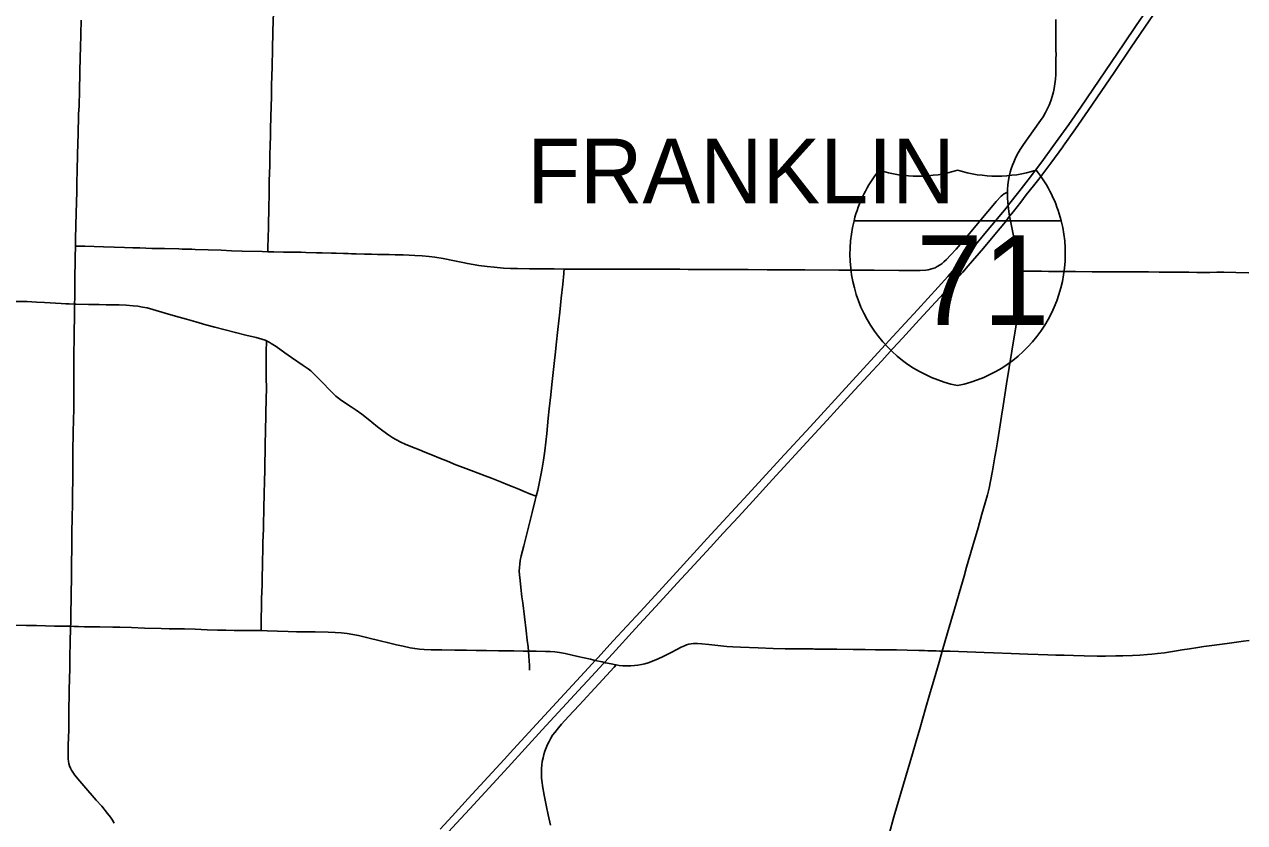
# Model space of a CAD drawing. Extents: x 1815539 to 1947826, y 273303 to 993194.
# Drawn here: x 1909139 to 1926135, y 915807 to 926931 of the extents above; entities that cross this region are included whole.
import ezdxf

# ---------------------------------------------------------------- set-up
doc = ezdxf.new("R2010")
doc.units = 0
for name, color, linetype in [('GM_X_County_Road', 7, 'Continuous'), ('GM_X_Interstate_Route', 7, 'Continuous'), ('GM_X_Interstate_Shield', 7, 'Continuous'), ('GM_X_State_Route', 7, 'Continuous'), ('GM_X_Township_Road', 7, 'Continuous'), ('GM_X_Township_Text', 7, 'Continuous')]:
    doc.layers.add(name, color=color, linetype=linetype)

msp = doc.modelspace()

# ---------------------------------------------------------------- linework, layer by layer
at = {"layer": 'GM_X_County_Road'}
for points in [[(1909852, 923839), (1909853, 923944), (1909861, 924304), (1909869, 924599), (1909872, 924714), (1909876, 924911), (1909884, 925288), (1909887, 925386), (1909895, 925681), (1909900, 925796), (1909908, 926009), (1909913, 926255), (1909917, 926484), (1909921, 926599), (1909925, 926795), (1909930, 926992)], [(1909839, 923031), (1909841, 923127), (1909842, 923288), (1909844, 923452), (1909846, 923583), (1909848, 923698), (1909851, 923829), (1909852, 923839)], [(1907174, 923151), (1907342, 923130), (1907473, 923114), (1907783, 923079), (1907946, 923061), (1908028, 923054), (1908093, 923053), (1908225, 923054), (1908569, 923063), (1908766, 923067), (1908881, 923068), (1909061, 923068), (1909176, 923067), (1909307, 923062), (1909421, 923055), (1909651, 923040), (1909715, 923038), (1909764, 923035), (1909828, 923032), (1909839, 923031)], [(1909783, 918543), (1909784, 918578), (1909788, 918742), (1909790, 918922), (1909796, 919299), (1909797, 919397), (1909799, 919660), (1909802, 919824), (1909806, 920086), (1909808, 920217), (1909811, 920397), (1909813, 920578), (1909813, 920725), (1909814, 920840), (1909815, 920988), (1909818, 921233), (1909822, 921430), (1909826, 921561), (1909829, 921807), (1909830, 921939), (1909830, 922086), (1909830, 922217), (1909830, 922331), (1909833, 922561), (1909838, 922937), (1909839, 923031)], [(1909839, 923031), (1909845, 923031), (1909860, 923031), (1910033, 923029), (1910082, 923028), (1910180, 923027), (1910278, 923024), (1910360, 923024), (1910458, 923021), (1910556, 923017), (1910654, 923010), (1910719, 923002), (1910784, 922992), (1910848, 922979), (1910927, 922959), (1911100, 922908), (1911242, 922867), (1911399, 922822), (1911526, 922786), (1911667, 922746), (1911794, 922710), (1912079, 922636), (1912223, 922601), (1912366, 922566), (1912445, 922545), (1912492, 922529), (1912511, 922521)], [(1912511, 922521), (1912522, 922517), (1912551, 922502), (1912578, 922486), (1912646, 922440), (1912766, 922354), (1912860, 922288), (1913023, 922178), (1913090, 922131), (1913129, 922101), (1913165, 922068), (1913224, 922011), (1913292, 921940), (1913392, 921832), (1913439, 921785), (1913475, 921752), (1913514, 921720), (1913554, 921692), (1913692, 921603), (1913759, 921557), (1913839, 921498), (1913903, 921448), (1913979, 921386), (1914056, 921325), (1914134, 921265), (1914215, 921208), (1914269, 921171), (1914312, 921146), (1914384, 921108), (1914444, 921079), (1914520, 921048), (1914642, 921000), (1914718, 920970), (1914823, 920927), (1914912, 920891), (1915033, 920842), (1915149, 920795), (1915212, 920771), (1915361, 920715), (1915557, 920640), (1915647, 920606), (1915783, 920550), (1915874, 920513), (1915934, 920489), (1916024, 920453), (1916099, 920423), (1916190, 920386), (1916269, 920357)], [(1916161, 918197), (1916155, 918255), (1916144, 918350), (1916128, 918480), (1916105, 918676), (1916080, 918871), (1916070, 918952), (1916054, 919082), (1916043, 919180), (1916035, 919262), (1916033, 919311), (1916034, 919361), (1916039, 919410), (1916047, 919459), (1916061, 919523), (1916097, 919666), (1916153, 919889), (1916184, 920016), (1916211, 920127), (1916255, 920301), (1916269, 920357)], [(1910391, 915798), (1910366, 915841), (1910339, 915882), (1910299, 915934), (1910216, 916035), (1910141, 916122), (1909968, 916319), (1909882, 916418), (1909841, 916470), (1909813, 916510), (1909796, 916539), (1909781, 916568), (1909769, 916598), (1909759, 916629), (1909753, 916661), (1909749, 916694), (1909748, 916743), (1909751, 916891), (1909753, 916989), (1909757, 917104), (1909758, 917186), (1909759, 917251), (1909759, 917415), (1909763, 917563), (1909765, 917661), (1909770, 917956), (1909773, 918153), (1909777, 918284), (1909779, 918366), (1909781, 918480), (1909783, 918543)], [(1918287, 918252), (1918289, 918253), (1918333, 918273), (1918363, 918285), (1918395, 918294), (1918428, 918299), (1918461, 918302), (1918515, 918302), (1918576, 918298), (1918674, 918289), (1918923, 918263), (1919006, 918255), (1919114, 918250), (1919360, 918241), (1919570, 918235), (1919734, 918231), (1919849, 918229), (1919931, 918228), (1920012, 918228), (1920062, 918227), (1920127, 918227), (1920144, 918226), (1920455, 918223), (1920685, 918220), (1920701, 918220), (1920736, 918220), (1920849, 918218), (1920992, 918217), (1921119, 918217), (1921201, 918216)], [(1921924, 918198), (1921946, 918198), (1922036, 918196), (1922149, 918193), (1922394, 918183), (1922509, 918179), (1922640, 918174), (1922886, 918164), (1923000, 918159), (1923115, 918156), (1923262, 918151), (1923393, 918146), (1923508, 918143), (1923622, 918140), (1923753, 918136), (1923901, 918132), (1924081, 918128), (1924196, 918127), (1924343, 918130), (1924441, 918132), (1924572, 918135), (1924676, 918141), (1924785, 918148), (1924845, 918153), (1924921, 918162), (1925019, 918175), (1925186, 918201), (1925264, 918213), (1925367, 918230), (1925484, 918248), (1925568, 918261), (1925680, 918275), (1925891, 918304), (1926118, 918334), (1926198, 918346)], [(1916161, 918197), (1916266, 918196), (1916396, 918194), (1916461, 918192), (1916527, 918186), (1916592, 918178), (1916673, 918163), (1916849, 918124), (1917025, 918083), (1917056, 918076)], [(1917380, 918005), (1917425, 917999), (1917474, 917994), (1917523, 917993), (1917588, 917993), (1917637, 917997), (1917685, 918003), (1917733, 918011), (1917781, 918022), (1917828, 918036), (1917889, 918058), (1917965, 918090), (1918039, 918124), (1918156, 918182), (1918287, 918252)], [(1921201, 918216), (1921285, 918215), (1921436, 918210), (1921597, 918206), (1921676, 918204), (1921724, 918202), (1921838, 918199), (1921887, 918198), (1921924, 918198)], [(1917056, 918076), (1917070, 918073), (1917091, 918068), (1917185, 918047), (1917218, 918039), (1917235, 918035), (1917313, 918018), (1917377, 918006), (1917380, 918005)]]:
    msp.add_lwpolyline(points, dxfattribs=at)
at = {"layer": 'GM_X_Interstate_Route'}
for points in [[(1923602, 925224), (1923610, 925234), (1923780, 925475), (1923958, 925731), (1924317, 926260), (1924556, 926613), (1925118, 927441), (1925224, 927597), (1925284, 927685), (1925431, 927902), (1925578, 928120), (1925818, 928472), (1926030, 928784), (1926120, 928917), (1926205, 929042)], [(1914932, 915718), (1915099, 915899), (1915320, 916142), (1915598, 916443), (1915820, 916685), (1915953, 916830), (1916274, 917181), (1916552, 917483), (1916997, 917965), (1917091, 918068), (1917099, 918077), (1917126, 918105), (1917342, 918339), (1917719, 918750), (1918075, 919137), (1918274, 919354), (1918651, 919766), (1918873, 920007), (1919218, 920381), (1919672, 920877), (1920083, 921323), (1920626, 921916), (1920926, 922242), (1921237, 922580), (1921581, 922955), (1921869, 923269), (1922001, 923416), (1922208, 923649), (1922389, 923861), (1922589, 924100), (1922694, 924226), (1922736, 924277), (1922790, 924344), (1922808, 924366), (1922840, 924408), (1922848, 924418), (1922992, 924597), (1923122, 924766), (1923310, 925015), (1923465, 925227), (1923685, 925534), (1923854, 925776), (1924451, 926659), (1924627, 926916), (1924903, 927324)], [(1922210, 923480), (1922285, 923566), (1922499, 923814), (1922658, 924002), (1922804, 924181), (1922813, 924193), (1922863, 924257), (1922915, 924322), (1922967, 924390), (1923018, 924453), (1923095, 924555), (1923197, 924682), (1923267, 924774), (1923435, 924996), (1923602, 925224)], [(1918355, 919277), (1918695, 919648), (1918873, 919841), (1919085, 920069), (1919284, 920287), (1919561, 920590), (1920038, 921109), (1920316, 921410), (1920460, 921567), (1920703, 921834), (1921081, 922244), (1921237, 922413), (1921369, 922558), (1921602, 922812), (1921890, 923127), (1922122, 923381), (1922210, 923480)], [(1916915, 917710), (1916986, 917787), (1917202, 918021), (1917218, 918039), (1917330, 918161), (1917653, 918511), (1917986, 918873), (1918285, 919201), (1918355, 919277)], [(1911986, 912380), (1912025, 912417), (1912151, 912542), (1912323, 912715), (1912448, 912846), (1913169, 913631), (1913524, 914017), (1914001, 914537), (1914234, 914790), (1914468, 915044), (1914789, 915395), (1915100, 915733), (1915344, 915999), (1915665, 916350), (1915876, 916579), (1916353, 917099), (1916915, 917710)]]:
    msp.add_lwpolyline(points, dxfattribs=at)
at = {"layer": 'GM_X_Interstate_Shield'}
for p, q in [((1920695, 924195), (1923581, 924195)), ((1923581, 924195), (1920695, 924195)), ((1923581, 924195), (1920695, 924195))]:
    msp.add_line(p, q, dxfattribs=at)
for centre, start, end in [((1922513, 923735), 141.669, 165.8066), ((1921590, 926691), 253.0091, 286.9909), ((1922686, 926691), 253.0091, 286.9909), ((1921763, 923735), 14.1934, 38.331), ((1922513, 923735), 165.8066, 258.463), ((1921763, 923735), 281.537, 14.1934)]:
    msp.add_arc(centre, 1875, start, end, dxfattribs=at)
at = {"layer": 'GM_X_State_Route'}
for points in [[(1923508, 926469), (1923509, 926493), (1923508, 926592), (1923507, 926739), (1923507, 927001)], [(1922964, 922819), (1922983, 922943), (1923010, 923122), (1923017, 923187), (1923021, 923252), (1923022, 923317), (1923020, 923382), (1923014, 923448), (1923008, 923495), (1923003, 923529), (1922975, 923690), (1922940, 923867), (1922888, 924124), (1922863, 924257), (1922858, 924285), (1922845, 924367), (1922840, 924408), (1922836, 924448), (1922832, 924514), (1922831, 924563), (1922832, 924593), (1922833, 924629), (1922839, 924695), (1922848, 924760), (1922856, 924809), (1922872, 924873), (1922885, 924920), (1922901, 924967), (1922919, 925013), (1922940, 925058), (1922969, 925116), (1923010, 925188), (1923054, 925257), (1923110, 925338), (1923293, 925590), (1923329, 925645), (1923361, 925701), (1923391, 925759), (1923411, 925804), (1923435, 925865), (1923455, 925927), (1923473, 925990), (1923484, 926037), (1923494, 926102), (1923502, 926166), (1923505, 926232), (1923508, 926395), (1923508, 926469)], [(1921187, 915666), (1921250, 915887), (1921383, 916343), (1921509, 916768), (1921560, 916941), (1921612, 917114), (1921697, 917413), (1921747, 917587), (1921810, 917807), (1921879, 918044), (1921924, 918198), (1921997, 918453), (1922043, 918611), (1922093, 918784), (1922181, 919082), (1922227, 919240), (1922263, 919366), (1922344, 919650), (1922422, 919917), (1922477, 920106), (1922523, 920263), (1922554, 920374), (1922577, 920469), (1922597, 920565), (1922623, 920710), (1922657, 920904), (1922674, 921000), (1922692, 921114), (1922720, 921292), (1922749, 921470), (1922772, 921616), (1922820, 921924), (1922892, 922377), (1922948, 922716), (1922964, 922819)]]:
    msp.add_lwpolyline(points, dxfattribs=at)
at = {"layer": 'GM_X_Township_Road'}
for points in [[(1912530, 923763), (1912532, 923817), (1912535, 923964), (1912538, 924095), (1912546, 924407), (1912548, 924538), (1912551, 924752), (1912556, 924965), (1912560, 925096), (1912564, 925260), (1912567, 925359), (1912569, 925474), (1912573, 925638), (1912578, 925792), (1912580, 925917), (1912580, 925983), (1912583, 926097), (1912585, 926196), (1912589, 926360), (1912594, 926573), (1912602, 926836), (1912607, 927099)], [(1921723, 923511), (1921730, 923511), (1921762, 923518), (1921793, 923528), (1921823, 923540), (1921853, 923555), (1921895, 923580), (1921921, 923599), (1921947, 923620), (1921983, 923653), (1922039, 923713), (1922116, 923798), (1922201, 923898), (1922297, 924010), (1922561, 924324), (1922632, 924413), (1922676, 924463), (1922743, 924535), (1922766, 924557), (1922779, 924567), (1922794, 924575), (1922832, 924593)], [(1909852, 923839), (1909914, 923839), (1909979, 923840), (1910110, 923836), (1910241, 923831), (1910389, 923825), (1910536, 923821), (1910651, 923818), (1910749, 923815), (1910831, 923812), (1910913, 923809), (1910978, 923808), (1911093, 923806), (1911289, 923801), (1911339, 923800), (1911470, 923797), (1911519, 923796), (1911699, 923791), (1911879, 923784), (1912026, 923777), (1912174, 923773), (1912452, 923765), (1912530, 923763)], [(1912530, 923763), (1912534, 923763), (1912616, 923761), (1912747, 923758), (1912846, 923757), (1912993, 923755), (1913058, 923753), (1913206, 923749), (1913288, 923748), (1913419, 923744), (1913484, 923743), (1913582, 923740), (1913648, 923737), (1913697, 923735), (1913762, 923732), (1913877, 923729), (1913975, 923727), (1914057, 923725), (1914123, 923724), (1914221, 923722), (1914302, 923721), (1914368, 923720), (1914417, 923719), (1914499, 923716), (1914580, 923712), (1914679, 923706), (1914776, 923697), (1914858, 923686), (1914971, 923667), (1915132, 923635), (1915244, 923613), (1915309, 923601), (1915470, 923573), (1915584, 923557), (1915681, 923546), (1915812, 923535), (1915910, 923529), (1916009, 923527), (1916173, 923525), (1916369, 923523), (1916517, 923523), (1916659, 923521)], [(1916269, 920357), (1916291, 920440), (1916333, 920648), (1916352, 920745), (1916370, 920858), (1916387, 920987), (1916414, 921231), (1916436, 921442), (1916449, 921573), (1916471, 921767), (1916487, 921914), (1916520, 922206), (1916538, 922369), (1916547, 922467), (1916569, 922678), (1916596, 922922), (1916607, 923020), (1916617, 923118), (1916638, 923313), (1916654, 923459), (1916655, 923476), (1916659, 923521)], [(1916659, 923521), (1916730, 923520), (1916845, 923520), (1916992, 923521), (1917090, 923521), (1917189, 923521), (1917402, 923520), (1917500, 923520), (1917730, 923519), (1918008, 923520), (1918123, 923520), (1918271, 923518), (1918385, 923517), (1918598, 923517), (1918779, 923516), (1919221, 923513), (1919484, 923512), (1919763, 923511), (1920008, 923510), (1920484, 923508), (1920746, 923508), (1920976, 923507), (1921320, 923502), (1921517, 923500), (1921615, 923503), (1921697, 923507), (1921723, 923511)], [(1923008, 923495), (1923044, 923494), (1923143, 923492), (1923307, 923490), (1923405, 923489), (1923667, 923486), (1923782, 923486), (1924012, 923485), (1924258, 923483), (1924455, 923483), (1924619, 923482), (1924799, 923482), (1924947, 923480), (1925078, 923478), (1925242, 923477), (1925357, 923476), (1925472, 923475), (1925603, 923474), (1925651, 923475), (1925749, 923476), (1925847, 923477), (1926011, 923474), (1926192, 923471)], [(1912435, 918484), (1912436, 918509), (1912436, 918525), (1912437, 918576), (1912438, 918629), (1912439, 918697), (1912441, 918767), (1912443, 918852), (1912443, 918894), (1912444, 918933), (1912446, 919015), (1912449, 919129), (1912452, 919260), (1912454, 919358), (1912454, 919424), (1912460, 919636), (1912462, 919717), (1912468, 919896), (1912469, 919946), (1912471, 920011), (1912473, 920125), (1912474, 920207), (1912477, 920371), (1912485, 920583), (1912488, 920698), (1912490, 920812), (1912493, 920992), (1912494, 921091), (1912497, 921254), (1912502, 921500), (1912508, 921729), (1912510, 921844), (1912509, 922024), (1912507, 922302), (1912507, 922400), (1912510, 922482), (1912511, 922521)], [(1908933, 918560), (1909163, 918556), (1909310, 918552), (1909557, 918546), (1909688, 918543), (1909737, 918543), (1909759, 918543), (1909783, 918543)], [(1909783, 918543), (1909831, 918542), (1909895, 918539), (1909977, 918537), (1910075, 918535), (1910190, 918534), (1910371, 918530), (1910469, 918529), (1910633, 918524), (1910814, 918519), (1911043, 918513), (1911158, 918510), (1911257, 918509), (1911371, 918506), (1911519, 918501), (1911683, 918496), (1911830, 918491), (1911945, 918488), (1912060, 918485), (1912125, 918484), (1912289, 918485), (1912404, 918484), (1912435, 918484)], [(1912435, 918484), (1912519, 918481), (1912666, 918477), (1912814, 918470), (1912929, 918467), (1913191, 918464), (1913371, 918459), (1913470, 918456), (1913551, 918451), (1913633, 918442), (1913714, 918430), (1913794, 918414), (1913906, 918388), (1914113, 918337), (1914193, 918318), (1914321, 918287), (1914416, 918264), (1914513, 918244), (1914577, 918233), (1914642, 918225), (1914708, 918220), (1914806, 918216), (1914954, 918213), (1915134, 918211), (1915299, 918209), (1915430, 918207), (1915578, 918205), (1915742, 918202), (1915955, 918199), (1916086, 918197), (1916161, 918197)], [(1916176, 917934), (1916175, 917950), (1916175, 917997), (1916166, 918125), (1916161, 918197)], [(1916347, 916391), (1916344, 916432), (1916341, 916498), (1916342, 916563), (1916346, 916612), (1916353, 916661), (1916363, 916709), (1916375, 916757), (1916390, 916804), (1916407, 916850), (1916426, 916895), (1916447, 916939), (1916471, 916982), (1916497, 917024), (1916526, 917064), (1916577, 917128), (1916619, 917178), (1916720, 917285), (1916865, 917442), (1917142, 917743), (1917352, 917974), (1917380, 918005)], [(1916467, 915773), (1916436, 915917), (1916412, 916029), (1916380, 916189), (1916356, 916318), (1916349, 916367), (1916347, 916391)]]:
    msp.add_lwpolyline(points, dxfattribs=at)

# ---------------------------------------------------------------- texts
at = {"layer": 'GM_X_Interstate_Shield'}
msp.add_text('71', height=1250, dxfattribs=at).set_placement((1921560, 922741))
at = {"layer": 'GM_X_Township_Text'}
msp.add_text('FRANKLIN', height=900, rotation=0, dxfattribs=at).set_placement((1916144, 924438))

doc.saveas('drawing.dxf')
